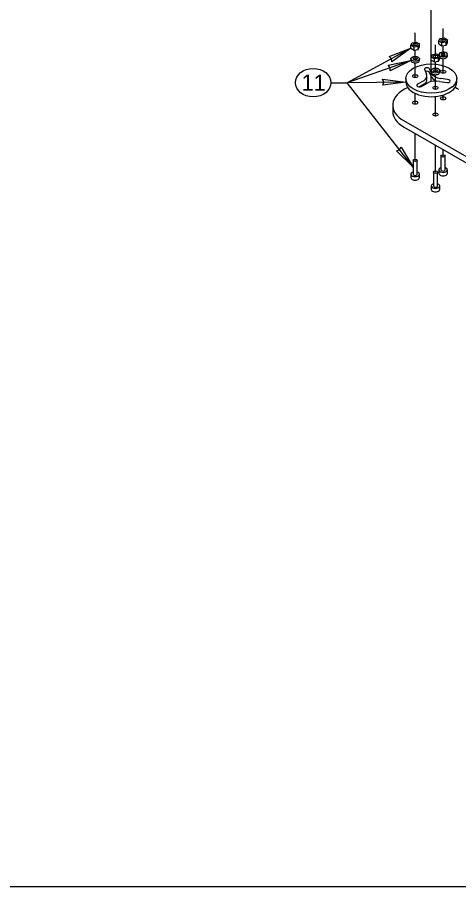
# Model space of a CAD drawing. Extents: x 99862 to 104211, y 98939 to 105076.
# Drawn here: x 101379 to 101813, y 103000 to 103854 of the extents above; entities that cross this region are included whole.
import ezdxf

# ---------------------------------------------------------------- set-up
doc = ezdxf.new("R2010")
doc.units = 0
for name, color, linetype in [('Level 1', 7, 'Continuous'), ('Level 11', 7, 'Continuous'), ('Level 12', 7, 'Continuous'), ('Level 15', 7, 'Continuous'), ('Level 20', 7, 'Continuous'), ('Level 21', 7, 'Continuous'), ('Level 8', 7, 'Continuous')]:
    doc.layers.add(name, color=color, linetype=linetype)

msp = doc.modelspace()

# ---------------------------------------------------------------- linework, layer by layer
at = {"layer": 'Level 1'}
msp.add_lwpolyline([(99862, 102999.5), (103151, 102999.5), (103151, 105075.5), (99862, 105075.5)], close=True, dxfattribs=at)
at = {"layer": 'Level 11'}
for p, q in [((101766.77, 103829.44), (101770.95, 103830.09)), ((101770.95, 103830.09), (101774.02, 103828.32)), ((101793.09, 103831.23), (101794.21, 103833.65)), ((101793.09, 103828.32), (101793.09, 103831.23)), ((101796.15, 103829.46), (101793.09, 103831.23)), ((101794.21, 103833.65), (101798.39, 103834.29)), ((101800.33, 103830.11), (101796.15, 103829.46)), ((101798.39, 103834.29), (101801.46, 103832.53)), ((101801.46, 103832.53), (101800.33, 103830.11)), ((101800.33, 103827.2), (101800.33, 103830.11)), ((101801.46, 103829.62), (101801.46, 103832.53)), ((101765.65, 103827.03), (101766.77, 103829.44)), ((101765.65, 103824.12), (101765.65, 103827.03)), ((101768.71, 103825.26), (101765.65, 103827.03)), ((101765.65, 103824.12), (101768.71, 103822.35)), ((101772.9, 103825.91), (101768.71, 103825.26)), ((101768.71, 103822.35), (101768.71, 103825.26)), ((101768.71, 103822.35), (101772.9, 103823)), ((101774.02, 103828.32), (101772.9, 103825.91)), ((101772.9, 103823), (101772.9, 103825.91)), ((101772.9, 103823), (101774.02, 103825.41)), ((101774.02, 103825.41), (101774.02, 103828.32)), ((101793.09, 103828.32), (101796.15, 103826.55)), ((101796.15, 103826.55), (101796.15, 103829.46)), ((101796.15, 103826.55), (101800.33, 103827.2)), ((101800.33, 103827.2), (101801.46, 103829.62)), ((101765.67, 103813.79), (101765.67, 103812.09)), ((101774, 103812.09), (101774, 103813.79)), ((101785.64, 103815.42), (101786.76, 103817.83)), ((101785.64, 103812.51), (101785.64, 103815.42)), ((101788.7, 103813.65), (101785.64, 103815.42)), ((101786.76, 103817.83), (101790.94, 103818.48)), ((101792.88, 103814.29), (101788.7, 103813.65)), ((101788.7, 103810.74), (101788.7, 103813.65)), ((101790.94, 103818.48), (101794, 103816.71)), ((101794, 103816.71), (101792.88, 103814.29)), ((101792.88, 103811.38), (101792.88, 103814.29)), ((101792.88, 103811.38), (101794, 103813.8)), ((101793.18, 103817.99), (101793.18, 103817.19)), ((101794, 103813.8), (101794, 103816.71)), ((101801.51, 103816.29), (101801.51, 103817.99)), ((101785.64, 103812.51), (101788.7, 103810.74)), ((101788.7, 103810.74), (101792.88, 103811.38)), ((101778.83, 103803.45), (101781.05, 103798.49)), ((101781.44, 103793.35), (101781.44, 103796.76)), ((101785.81, 103799.64), (101784.04, 103803.45)), ((101785.81, 103796.23), (101784.04, 103800.05)), ((101785.65, 103802.18), (101785.65, 103800.48)), ((101793.99, 103800.48), (101793.99, 103802.18)), ((101760.68, 103794.31), (101760.68, 103790.9)), ((101778.36, 103792.21), (101772.24, 103788.67)), ((101778.36, 103788.81), (101773.71, 103786.12)), ((101775.92, 103786.55), (101782.84, 103790.54)), ((101793.61, 103791.58), (101801.52, 103790.35)), ((101801.52, 103793.36), (101794.91, 103794.38)), ((101810.68, 103790.9), (101810.68, 103794.31)), ((101767.75, 103713.86), (101767.75, 103700.26)), ((101771.92, 103700.26), (101771.92, 103713.86)), ((101795.19, 103718.07), (101795.19, 103704.46)), ((101799.36, 103704.46), (101799.36, 103718.07)), ((101787.74, 103702.25), (101787.74, 103688.65)), ((101791.9, 103688.65), (101791.9, 103702.25)), ((101793.11, 103704.46), (101793.11, 103701.06)), ((101801.44, 103701.06), (101801.44, 103704.46)), ((101765.67, 103700.26), (101765.67, 103696.85)), ((101774, 103696.85), (101774, 103700.26)), ((101785.65, 103688.65), (101785.65, 103685.24)), ((101793.99, 103685.24), (101793.99, 103688.65))]:
    msp.add_line(p, q, dxfattribs=at)
for centre, major_axis in [((101797.27, 103831.88), (2.27, 0)), ((101769.83, 103827.67), (2.27, 0)), ((101769.83, 103813.79), (-4.17, 0)), ((101769.83, 103813.79), (-2.08, 0)), ((101789.82, 103816.06), (2.27, 0)), ((101785.68, 103794.31), (-25, 0)), ((101789.82, 103802.18), (-4.17, 0)), ((101769.83, 103796.76), (-2.6, 0)), ((101789.82, 103802.18), (-2.08, 0)), ((101797.34, 103800.96), (-2.6, 0)), ((101789.82, 103785.14), (-2.6, 0)), ((101797.27, 103718.07), (-2.08, 0)), ((101769.83, 103713.86), (-2.08, 0)), ((101789.82, 103702.25), (-2.08, 0))]:
    msp.add_ellipse(centre, major_axis=major_axis, ratio=0.57735, dxfattribs=at)
for centre, major_axis, start_param, end_param in [((101769.83, 103812.09), (-2.08, 0), 3.926991, 5.497787), ((101797.34, 103817.99), (-4.17, 0), 0.640708, 6.732556), ((101797.34, 103816.29), (-4.17, 0), 0.640708, 3.141593), ((101797.34, 103817.99), (-2.08, 0), 0.014662, 6.296698), ((101797.34, 103816.29), (-2.08, 0), 3.926991, 5.497787), ((101769.83, 103812.09), (-4.17, 0), 0, 3.141593), ((101781.43, 103803.45), (-2.6, 0), 3.141593, 6.283185), ((101769.83, 103796.76), (-11.61, 0), 2.396309, 3.403392), ((101781.43, 103800.05), (-2.6, 0), 3.141593, 5.379094), ((101789.82, 103800.48), (-4.17, 0), 6.283185, 9.424778), ((101797.27, 103801), (-11.71, 0), 0.203445, 1.367352), ((101797.27, 103797.6), (-11.71, 0), 0.203445, 1.005854), ((101789.82, 103800.48), (-2.08, 0), 3.926991, 5.497787), ((101785.68, 103790.9), (-25, 0), 6.283185, 9.424778), ((101774.08, 103787.61), (-2.6, 0), 5.497787, 8.63938), ((101769.83, 103793.35), (-11.61, 0), 2.396309, 3.141593), ((101789.92, 103785.16), (-11.71, 0), 4.392235, 5.361438), ((101801.52, 103791.86), (-2.6, 0), 1.570796, 4.712389), ((101769.83, 103700.26), (-4.17, 0), 5.235988, 10.471976), ((101797.27, 103704.46), (-4.17, 0), 5.235988, 10.471976), ((101797.27, 103704.46), (-2.08, 0), 6.283185, 9.424778), ((101769.83, 103696.85), (-4.17, 0), 6.283185, 9.424778), ((101769.83, 103700.26), (-2.08, 0), 0, 3.141593), ((101797.27, 103701.06), (-4.17, 0), 6.283185, 9.424778), ((101789.82, 103688.65), (-4.17, 0), 5.235988, 10.471976), ((101789.82, 103685.24), (-4.17, 0), 6.283185, 9.424778), ((101789.82, 103688.65), (-2.08, 0), 6.283185, 9.424778)]:
    msp.add_ellipse(centre, major_axis=major_axis, ratio=0.57735, start_param=start_param, end_param=end_param, dxfattribs=at)
at = {"layer": 'Level 12'}
msp.add_line((102255.59, 103465.87), (101758.84, 103752.66), dxfattribs=at)
at = {"layer": 'Level 15'}
for p, q in [((101785.68, 103791.46), (101785.68, 103980.92)), ((101769.83, 103826.36), (101769.83, 103839.2)), ((101797.27, 103830.57), (101797.27, 103843.41)), ((101765.65, 103824.12), (101703.06, 103790.27)), ((101769.83, 103812.58), (101769.83, 103822.52)), ((101789.82, 103814.75), (101789.82, 103827.59)), ((101797.27, 103816.79), (101797.27, 103826.73)), ((101797.27, 103799.46), (101797.27, 103813.89)), ((101765.67, 103812.09), (101703.06, 103790.27)), ((101769.83, 103795.25), (101769.83, 103809.68)), ((101789.82, 103800.97), (101789.82, 103810.91)), ((101789.82, 103783.64), (101789.82, 103798.07)), ((101687.06, 103790.27), (101703.06, 103790.27)), ((101760.68, 103790.9), (101703.06, 103790.27)), ((101767.75, 103707.06), (101703.06, 103790.27)), ((101769.83, 103769.1), (101769.83, 103779.74)), ((101789.82, 103757.49), (101789.82, 103776.67)), ((101797.34, 103773.3), (101797.34, 103778.14)), ((101769.83, 103713.86), (101769.83, 103740.12)), ((101789.82, 103702.25), (101789.82, 103728.58)), ((101797.27, 103718.07), (101797.27, 103724.28))]:
    msp.add_line(p, q, dxfattribs=at)
for points in [[(101765.65, 103824.12), (101746.99, 103810.63), (101746.5, 103813.76), (101744.15, 103815.88)], [(101765.67, 103812.09), (101745.09, 103801.76), (101745.11, 103804.92), (101743.13, 103807.39)], [(101760.68, 103790.9), (101737.88, 103787.67), (101738.9, 103790.66), (101737.81, 103793.64)], [(101767.75, 103707.06), (101751.38, 103723.25), (101754.39, 103724.25), (101756.09, 103726.92)]]:
    msp.add_lwpolyline(points, close=True, dxfattribs=at)
at = {"layer": 'Level 20'}
msp.add_ellipse((101669.56, 103790.27), major_axis=(-17.5, 0), ratio=0.8, dxfattribs=at)
at = {"layer": 'Level 21'}
msp.add_line((102255.59, 103459.67), (101758.84, 103746.47), dxfattribs=at)
for centre, start_param, end_param in [((101785.68, 103768.15), 1.672934, 1.7301), ((101785.68, 103768.15), 2.227977, 3.926991), ((101785.68, 103768.15), 0.785412, 0.913615), ((101785.68, 103761.96), 3.141593, 3.926991)]:
    msp.add_ellipse(centre, major_axis=(37.94, 0), ratio=0.57735, start_param=start_param, end_param=end_param, dxfattribs=at)
for centre in [(101769.83, 103770.6), (101797.34, 103774.81), (101789.82, 103758.99)]:
    msp.add_ellipse(centre, major_axis=(-2.6, 0), ratio=0.57735, dxfattribs=at)
at = {"layer": 'Level 8'}
msp.add_line((101747.73, 103768.15), (101747.73, 103761.96), dxfattribs=at)

# ---------------------------------------------------------------- texts
at = {"layer": 'Level 20'}
msp.add_text('11', height=16, dxfattribs=at).set_placement((101658.18, 103782.27))

doc.saveas('drawing.dxf')
